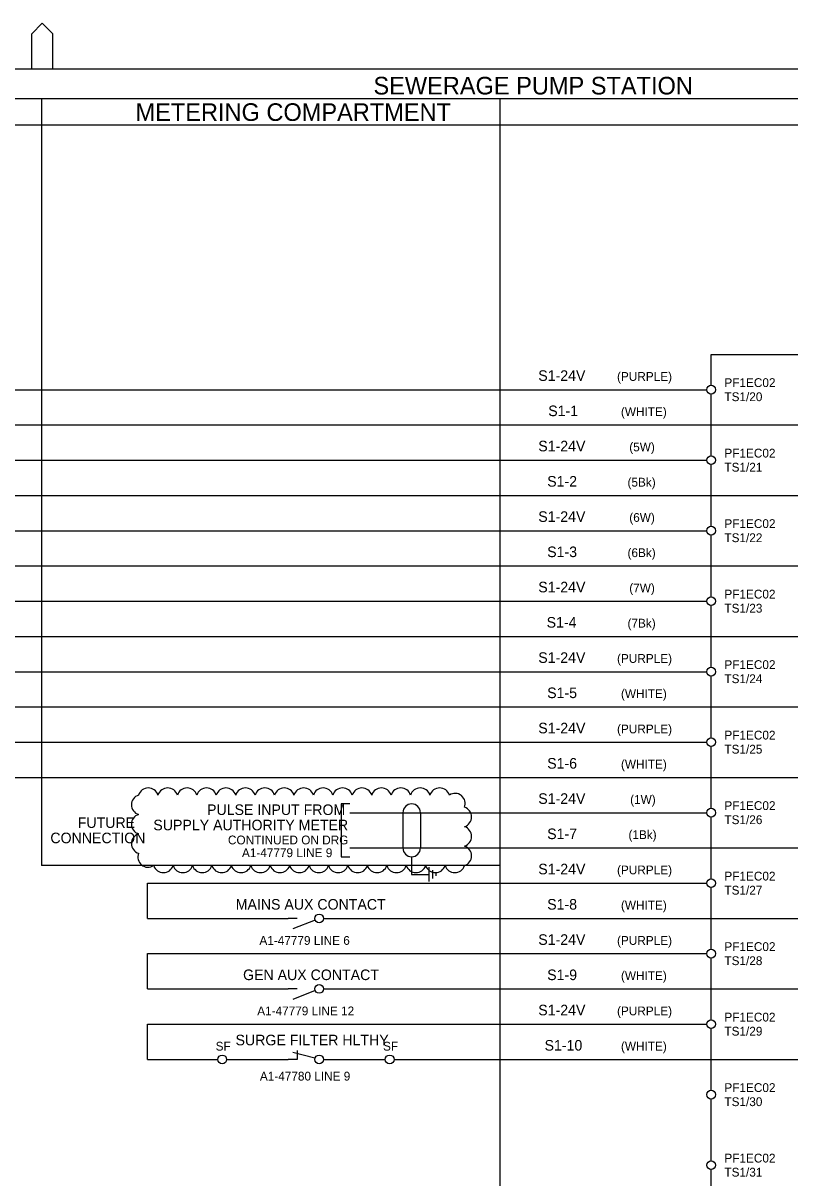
# Model space of a CAD drawing. Extents: x 0 to 841, y 0 to 594.
# Drawn here: x 414.7 to 632.3, y 266.4 to 594 of the extents above; entities that cross this region are included whole.
import ezdxf

# ---------------------------------------------------------------- set-up
doc = ezdxf.new("R2010")
doc.units = 0
for name, color, linetype in [('A1BORDER', 7, 'Continuous'), ('BASE', 7, 'Continuous'), ('Level 1', 7, 'Continuous'), ('Level 10', 7, 'Continuous'), ('Level 2', 7, 'Continuous'), ('Level 5', 7, 'Continuous'), ('Level 6', 7, 'Continuous')]:
    doc.layers.add(name, color=color, linetype=linetype)

msp = doc.modelspace()

# ---------------------------------------------------------------- linework, layer by layer
at = {"layer": 'A1BORDER'}
for p, q in [((417.19, 591), (420.19, 594)), ((423.19, 591), (420.19, 594)), ((417.19, 581), (417.19, 591)), ((423.19, 581), (423.19, 591)), ((28, 581), (829, 581))]:
    msp.add_line(p, q, dxfattribs=at)
at = {"layer": 'BASE'}
for p, q in [((507.5, 370), (608.75, 370)), ((507.5, 360), (685, 360))]:
    msp.add_line(p, q, dxfattribs=at)
at = {"layer": 'Level 1'}
for p, q in [((829, 572.5), (160, 572.5)), ((420, 572.5), (420, 355)), ((550, 572.5), (550, 57)), ((829, 565), (160, 565)), ((610, 491.25), (610, 500)), ((610, 500), (650, 500)), ((320, 490), (608.75, 490)), ((610, 471.25), (610, 488.75)), ((370, 480), (685, 480)), ((270, 470), (608.75, 470)), ((610, 451.25), (610, 468.75)), ((270, 460), (685, 460)), ((270, 450), (608.75, 450)), ((610, 431.25), (610, 448.75)), ((270, 440), (685, 440)), ((270, 430), (608.75, 430)), ((610, 411.25), (610, 428.75)), ((270, 420), (685, 420)), ((320, 410), (608.75, 410)), ((610, 391.25), (610, 408.75)), ((370, 400), (685, 400)), ((320, 390), (608.75, 390)), ((610, 371.25), (610, 388.75)), ((410, 380), (685, 380)), ((522.5, 370), (522.5, 360)), ((527.5, 370), (527.5, 360)), ((610, 351.25), (610, 368.75)), ((525, 357.5), (525, 352.5)), ((550, 355), (420, 355)), ((525, 352.5), (530, 352.5)), ((450, 350), (608.75, 350)), ((450, 340), (450, 350)), ((610, 331.25), (610, 348.75)), ((450, 340), (490, 340)), ((492.5, 340), (490, 340)), ((490, 340), (490, 340)), ((500, 340), (685, 340)), ((500, 340), (500, 340)), ((450, 330), (608.75, 330)), ((450, 320), (450, 330)), ((610, 311.25), (610, 328.75)), ((450, 320), (490, 320)), ((492.5, 320), (490, 320)), ((490, 320), (490, 320)), ((500, 320), (685, 320)), ((500, 320), (500, 320)), ((450, 310), (608.75, 310)), ((450, 300), (450, 310)), ((610, 291.25), (610, 308.75)), ((450, 300), (470, 300)), ((472.5, 300), (490, 300)), ((492.5, 300), (490, 300)), ((520, 300), (685, 300)), ((610, 271.25), (610, 288.75)), ((610, 251.25), (610, 268.75))]:
    msp.add_line(p, q, dxfattribs=at)
msp.add_lwpolyline([(507.5, 372.5), (505, 372.5), (505, 357.5), (507.5, 357.5)], dxfattribs=at)
for centre, radius, start, end in [((450.26, 374.13), 2.89, 17.5, 162.5), ((455.77, 374.13), 2.89, 17.5, 162.5), ((461.28, 374.13), 2.89, 17.5, 162.5), ((466.8, 374.13), 2.89, 17.5, 162.5), ((472.31, 374.13), 2.89, 17.5, 162.5), ((477.82, 374.13), 2.89, 17.5, 162.5), ((483.34, 374.13), 2.89, 17.5, 162.5), ((488.85, 374.13), 2.89, 17.5, 162.5), ((494.36, 374.13), 2.89, 17.5, 162.5), ((499.87, 374.13), 2.89, 17.5, 162.5), ((505.39, 374.13), 2.89, 17.5, 162.5), ((510.9, 374.13), 2.89, 17.5, 162.5), ((516.41, 374.13), 2.89, 17.5, 162.5), ((521.93, 374.13), 2.89, 17.5, 162.5), ((527.44, 374.13), 2.89, 17.5, 162.5), ((532.95, 374.13), 2.89, 17.5, 162.5), ((448.37, 372.24), 2.89, 107.5, 252.5), ((537.31, 372.59), 2.89, 338.6071, 123.6071), ((525, 370), 2.5, 0, 180), ((539.13, 368.78), 2.89, 287.5, 72.5), ((448.37, 366.73), 2.89, 107.5, 252.5), ((448.37, 361.22), 2.89, 107.5, 252.5), ((539.13, 363.27), 2.89, 287.5, 72.5), ((539.13, 357.76), 2.89, 287.5, 72.5), ((450.19, 357.41), 2.89, 158.6071, 303.6071), ((525, 360), 2.5, 180, 0), ((454.55, 355.87), 2.89, 197.5, 342.5), ((460.06, 355.87), 2.89, 197.5, 342.5), ((465.57, 355.87), 2.89, 197.5, 342.5), ((471.09, 355.87), 2.89, 197.5, 342.5), ((476.6, 355.87), 2.89, 197.5, 342.5), ((482.11, 355.87), 2.89, 197.5, 342.5), ((487.63, 355.87), 2.89, 197.5, 342.5), ((493.14, 355.87), 2.89, 197.5, 342.5), ((498.65, 355.87), 2.89, 197.5, 342.5), ((504.16, 355.87), 2.89, 197.5, 342.5), ((509.68, 355.87), 2.89, 197.5, 342.5), ((515.19, 355.87), 2.89, 197.5, 342.5), ((520.7, 355.87), 2.89, 197.5, 342.5), ((526.22, 355.87), 2.89, 197.5, 342.5), ((531.73, 355.87), 2.89, 197.5, 342.5), ((537.24, 355.87), 2.89, 197.5, 342.5)]:
    msp.add_arc(centre, radius, start, end, dxfattribs=at)
at = {"layer": 'Level 10'}
for p, q in [((530, 350.5), (530, 354.5)), ((531, 351.3), (531, 353.7)), ((532, 352.1), (532, 352.9)), ((497.59, 339.54), (491.25, 337)), ((497.59, 319.54), (491.25, 317)), ((497.54, 300.32), (491.25, 302)), ((492.5, 302.5), (492.5, 300))]:
    msp.add_line(p, q, dxfattribs=at)
for centre in [(610, 490), (610, 470), (610, 450), (610, 430), (610, 410), (610, 390), (610, 370), (610, 350), (498.75, 340), (610, 330), (498.75, 320), (610, 310), (498.75, 300), (610, 290), (610, 270)]:
    msp.add_circle(centre, 1.25, dxfattribs=at)
at = {"layer": 'Level 5'}
for centre in [(471.25, 300), (518.75, 300)]:
    msp.add_circle(centre, 1.25, dxfattribs=at)
at = {"layer": 'Level 6'}
msp.add_line((500, 300), (517.5, 300), dxfattribs=at)

# ---------------------------------------------------------------- texts
at = {"layer": 'Level 1'}
for s, height, p in [('SEWERAGE PUMP STATION', 5, (514.16, 573.75)), ('METERING COMPARTMENT', 5, (446.64, 566.25)), ('S1-24V', 3, (560.93, 492.5)), ('(PURPLE)', 2.5, (583.28, 492.5)), ('S1-1', 3, (563.76, 482.5)), ('(WHITE)', 2.5, (584.39, 482.5)), ('S1-24V', 3, (560.93, 472.5)), ('(5W)', 2.5, (586.76, 472.5)), ('PF1EC02', 2.5, (613.75, 470.75)), ('TS1/21', 2.5, (613.75, 466.75)), ('S1-2', 3, (563.46, 462.5)), ('(5Bk)', 2.5, (586.26, 462.5)), ('S1-24V', 3, (560.93, 452.5)), ('(6W)', 2.5, (586.76, 452.5)), ('PF1EC02', 2.5, (613.75, 450.75)), ('TS1/22', 2.5, (613.75, 446.75)), ('S1-3', 3, (563.46, 442.5)), ('(6Bk)', 2.5, (586.26, 442.5)), ('S1-24V', 3, (560.93, 432.5)), ('(7W)', 2.5, (586.76, 432.5)), ('PF1EC02', 2.5, (613.75, 430.75)), ('TS1/23', 2.5, (613.75, 426.75)), ('S1-4', 3, (563.31, 422.5)), ('(7Bk)', 2.5, (586.26, 422.5)), ('S1-24V', 3, (560.93, 412.5)), ('(PURPLE)', 2.5, (583.28, 412.5)), ('PF1EC02', 2.5, (613.75, 410.75)), ('TS1/24', 2.5, (613.75, 406.75)), ('S1-5', 3, (563.46, 402.5)), ('(WHITE)', 2.5, (584.4, 402.5)), ('S1-24V', 3, (560.93, 392.5)), ('(PURPLE)', 2.5, (583.28, 392.5)), ('PF1EC02', 2.5, (613.75, 390.75)), ('TS1/25', 2.5, (613.75, 386.75)), ('S1-6', 3, (563.46, 382.5)), ('(WHITE)', 2.5, (584.4, 382.5)), ('S1-24V', 3, (560.93, 372.5)), ('(1W)', 2.5, (587.01, 372.5)), ('PULSE INPUT FROM', 3, (466.94, 369.34)), ('PF1EC02', 2.5, (613.75, 370.75)), ('FUTURE', 3, (430.25, 365.67)), ('SUPPLY AUTHORITY METER', 3, (451.7, 365)), ('TS1/26', 2.5, (613.75, 366.75)), ('CONNECTION', 3, (422.48, 361.33)), ('S1-7', 3, (563.46, 362.5)), ('(1Bk)', 2.5, (586.52, 362.5)), ('CONTINUED ON DRG', 2.5, (472.87, 361)), ('A1-47779 LINE 9', 2.5, (476.85, 357.38)), ('S1-24V', 3, (560.93, 352.5)), ('(PURPLE)', 2.5, (583.28, 352.5)), ('S1-8', 3, (563.46, 342.5)), ('(WHITE)', 2.5, (584.4, 342.5)), ('S1-24V', 3, (560.93, 332.5)), ('(PURPLE)', 2.5, (583.28, 332.5)), ('S1-9', 3, (563.46, 322.5)), ('(WHITE)', 2.5, (584.4, 322.5)), ('S1-24V', 3, (560.93, 312.5)), ('(PURPLE)', 2.5, (583.28, 312.5)), ('SF', 2.5, (469.38, 302.5)), ('SF', 2.5, (516.88, 302.5)), ('S1-10', 3, (562.72, 302.5)), ('(WHITE)', 2.5, (584.4, 302.5))]:
    msp.add_text(s, height=height, dxfattribs=at).set_placement(p)
at = {"layer": 'Level 2'}
for s, p in [('PF1EC02', (613.75, 490.75)), ('TS1/20', (613.75, 486.75)), ('PF1EC02', (613.75, 350.75)), ('TS1/27', (613.75, 346.75)), ('PF1EC02', (613.75, 330.75)), ('TS1/28', (613.75, 326.75)), ('PF1EC02', (613.75, 310.75)), ('TS1/29', (613.75, 306.75)), ('PF1EC02', (613.75, 290.75)), ('TS1/30', (613.75, 286.75)), ('PF1EC02', (613.75, 270.75)), ('TS1/31', (613.75, 266.75))]:
    msp.add_text(s, height=2.5, dxfattribs=at).set_placement(p)
at = {"layer": 'Level 5'}
for s, height, p in [('MAINS AUX CONTACT', 3, (475.07, 342.5)), ('A1-47779 LINE 6', 2.5, (481.8, 332.5)), ('GEN AUX CONTACT', 3, (477.16, 322.5)), ('A1-47779 LINE 12', 2.5, (481.18, 312.5)), ('SURGE FILTER HLTHY', 3, (475.02, 304)), ('A1-47780 LINE 9', 2.5, (481.94, 294))]:
    msp.add_text(s, height=height, dxfattribs=at).set_placement(p)

doc.saveas('drawing.dxf')
